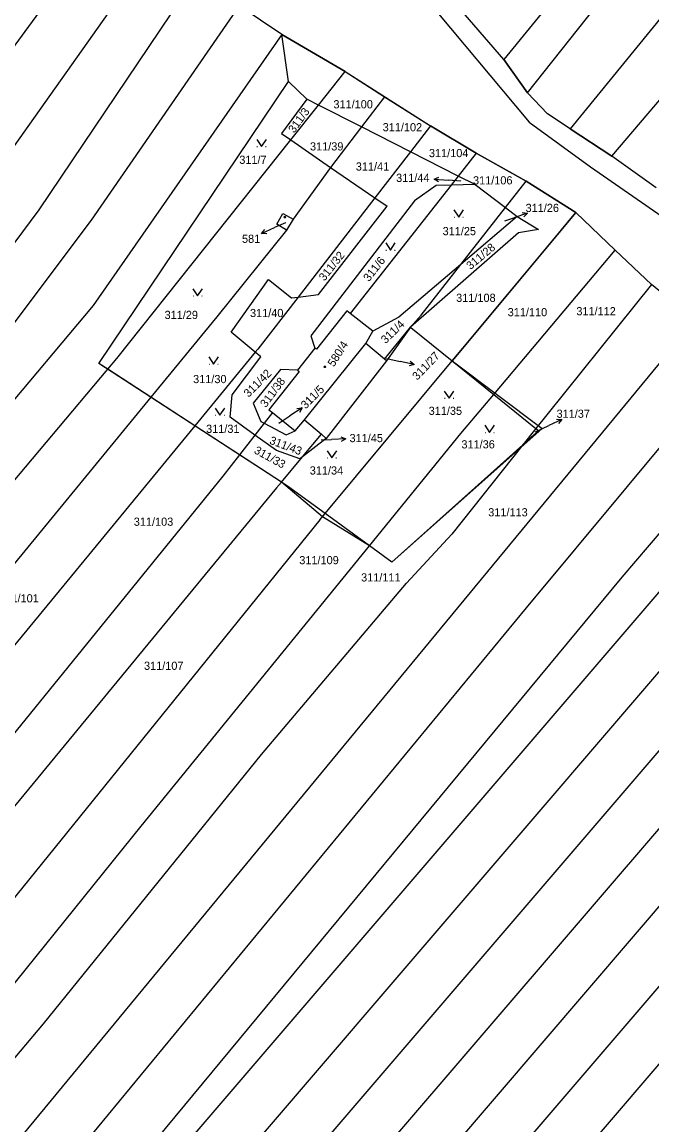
# Model space of a CAD drawing. Extents: x -580630 to -576196, y -1189024 to -1183567.
# Drawn here: x -579205 to -579073.9, y -1185934.4 to -1185704.7 of the extents above; entities that cross this region are included whole.
import ezdxf

# ---------------------------------------------------------------- set-up
doc = ezdxf.new("R2010")
doc.units = 0
for name, color, linetype in [('Vrstva 1', 7, 'Continuous'), ('Vrstva 16', 7, 'Continuous'), ('Vrstva 18', 7, 'Continuous'), ('Vrstva 19', 7, 'Continuous'), ('Vrstva 25', 7, 'Continuous'), ('Vrstva 4', 7, 'Continuous'), ('Vrstva 6', 7, 'Continuous'), ('Vrstva 63', 7, 'Continuous')]:
    doc.layers.add(name, color=color, linetype=linetype)

msp = doc.modelspace()

# ---------------------------------------------------------------- linework, layer by layer
at = {"layer": 'Vrstva 1'}
for p, q in [((-579043.29, -1185637.51), (-579104.75, -1185712.51)), ((-579099.79, -1185719.43), (-579070.36, -1185682.39)), ((-579131.33, -1185687.39), (-579099.45, -1185725.59)), ((-579082.26, -1185732.61), (-579044.89, -1185688.85)), ((-579061.52, -1185690.84), (-579090.91, -1185726.96)), ((-579104.75, -1185712.51), (-579114.98, -1185700.62)), ((-579150.91, -1185707.31), (-579159.8, -1185701.35)), ((-579137.74, -1185715.04), (-579150.91, -1185707.31)), ((-579104.75, -1185712.51), (-579099.79, -1185719.43)), ((-579137.74, -1185715.04), (-579129.57, -1185720.26)), ((-579189.01, -1185775.8), (-579149.58, -1185717.1)), ((-579149.58, -1185717.1), (-579145.75, -1185720.78)), ((-579095.65, -1185723.82), (-579099.79, -1185719.43)), ((-579145.75, -1185720.78), (-579151, -1185727.93)), ((-579143.3, -1185722.02), (-579145.75, -1185720.78)), ((-579129.57, -1185720.26), (-579119.98, -1185726.31)), ((-579134.36, -1185726.56), (-579143.3, -1185722.02)), ((-579090.91, -1185726.96), (-579095.65, -1185723.82)), ((-579110.49, -1185732.01), (-579119.98, -1185726.31)), ((-579099.45, -1185725.59), (-579086.66, -1185734.87)), ((-579151, -1185727.93), (-579149.06, -1185729.27)), ((-579124.17, -1185731.73), (-579134.36, -1185726.56)), ((-579090.91, -1185726.96), (-579082.26, -1185732.61)), ((-579149.06, -1185729.27), (-579140.77, -1185734.98)), ((-579114.22, -1185736.77), (-579124.17, -1185731.73)), ((-579100.08, -1185737.83), (-579110.49, -1185732.01)), ((-579072.99, -1185739.21), (-579082.26, -1185732.61)), ((-579140.77, -1185734.98), (-579131.58, -1185741.32)), ((-579086.66, -1185734.87), (-579070.88, -1185745.81)), ((-579110.71, -1185738.55), (-579114.22, -1185736.77)), ((-579089.72, -1185744.38), (-579100.08, -1185737.83)), ((-579118.79, -1185738.72), (-579123.31, -1185741.96)), ((-579115.7, -1185738.65), (-579118.79, -1185738.72)), ((-579110.71, -1185738.55), (-579115.7, -1185738.65)), ((-579110.71, -1185738.55), (-579104.39, -1185743.34)), ((-579123.31, -1185741.96), (-579144.91, -1185770.06)), ((-579131.58, -1185741.32), (-579129.03, -1185743.08)), ((-579151.98, -1185746.78), (-579150.71, -1185744.55)), ((-579150.71, -1185744.55), (-579148.6, -1185745.75)), ((-579143.3, -1185761.42), (-579129.03, -1185743.08)), ((-579104.39, -1185743.34), (-579101.94, -1185745.2)), ((-579089.72, -1185744.38), (-579081.53, -1185752.18)), ((-579149.99, -1185748.03), (-579151.98, -1185746.78)), ((-579148.6, -1185745.75), (-579149.99, -1185748.03)), ((-579101.94, -1185745.2), (-579113.64, -1185755.17)), ((-579101.94, -1185745.2), (-579097.53, -1185747.9)), ((-579101.63, -1185748.61), (-579124.18, -1185768.24)), ((-579097.53, -1185747.9), (-579101.63, -1185748.61)), ((-579081.53, -1185752.18), (-579073.99, -1185759.36)), ((-579113.64, -1185755.17), (-579126.56, -1185766.18)), ((-579161.51, -1185769.31), (-579153.73, -1185758.32)), ((-579153.73, -1185758.32), (-579148.93, -1185762.15)), ((-579064.92, -1185766.8), (-579073.99, -1185759.36)), ((-579148.93, -1185762.15), (-579147.54, -1185761.97)), ((-579147.54, -1185761.97), (-579143.3, -1185761.42)), ((-579137.43, -1185764.81), (-579143.75, -1185772.81)), ((-579136.69, -1185765.39), (-579137.43, -1185764.81)), ((-579132.02, -1185769.05), (-579136.69, -1185765.39)), ((-579126.56, -1185766.18), (-579132.02, -1185769.05)), ((-579156.46, -1185773.46), (-579161.51, -1185769.31)), ((-579144.91, -1185770.06), (-579144.05, -1185772.59)), ((-579133.45, -1185771.65), (-579132.02, -1185769.05)), ((-579124.18, -1185768.24), (-579129.12, -1185775.26)), ((-579124.18, -1185768.24), (-579124.08, -1185768.32)), ((-579124.08, -1185768.32), (-579115.45, -1185775.29)), ((-579129.57, -1185774.88), (-579133.45, -1185771.65)), ((-579161.29, -1185782.37), (-579155.32, -1185774.4)), ((-579155.32, -1185774.4), (-579156.46, -1185773.46)), ((-579144.05, -1185772.59), (-579147.68, -1185777.21)), ((-579143.75, -1185772.81), (-579144.05, -1185772.59)), ((-579187.16, -1185777), (-579189.01, -1185775.8)), ((-579178.19, -1185782.83), (-579187.16, -1185777)), ((-579151.24, -1185777.07), (-579156.93, -1185784.08)), ((-579147.68, -1185777.21), (-579151.24, -1185777.07)), ((-579129.12, -1185775.26), (-579141.71, -1185791.41)), ((-579129.12, -1185775.26), (-579129.57, -1185774.88)), ((-579115.45, -1185775.29), (-579106.82, -1185782.26)), ((-579147.32, -1185777.48), (-579153.63, -1185785.44)), ((-579147.68, -1185777.21), (-579147.32, -1185777.48)), ((-579169.06, -1185788.77), (-579178.19, -1185782.83)), ((-579161.69, -1185786.99), (-579161.29, -1185782.37)), ((-579106.82, -1185782.26), (-579098.03, -1185789.35)), ((-579156.93, -1185784.08), (-579155.32, -1185787.87)), ((-579153.63, -1185785.44), (-579152.89, -1185786.03)), ((-579152.89, -1185786.03), (-579148.15, -1185789.82)), ((-579080.09, -1185820.33), (-579049.55, -1185784.45)), ((-579156.55, -1185790.7), (-579161.69, -1185786.99)), ((-579155.32, -1185787.87), (-579154.62, -1185788.24)), ((-579154.62, -1185788.24), (-579150.06, -1185790.67)), ((-579148.15, -1185789.82), (-579146.19, -1185787.53)), ((-579146.19, -1185787.53), (-579142.7, -1185790.55)), ((-579043.07, -1185789.08), (-579516.28, -1186341.47)), ((-579159.77, -1185794.81), (-579169.06, -1185788.77)), ((-579152.08, -1185793.93), (-579156.55, -1185790.7)), ((-579150.06, -1185790.67), (-579148.15, -1185789.82)), ((-579142.7, -1185790.55), (-579141.71, -1185791.41)), ((-579097.45, -1185789.82), (-579100.76, -1185792.78)), ((-579098.03, -1185789.35), (-579097.45, -1185789.82)), ((-579141.71, -1185791.41), (-579146.66, -1185795.27)), ((-579100.76, -1185792.78), (-579128.06, -1185817.19)), ((-579560.3, -1186409.54), (-579034.2, -1185795.41)), ((-579151.03, -1185800.49), (-579159.77, -1185794.81)), ((-579147.17, -1185795.67), (-579152.08, -1185793.93)), ((-579146.66, -1185795.27), (-579147.17, -1185795.67)), ((-579025.51, -1185801.62), (-579550.65, -1186414.64)), ((-579149.73, -1185801.34), (-579151.03, -1185800.49)), ((-579141.9, -1185807.07), (-579149.73, -1185801.34)), ((-579541.04, -1186419.71), (-579016.85, -1185807.81)), ((-579132.7, -1185813.8), (-579141.9, -1185807.07)), ((-579128.06, -1185817.19), (-579132.7, -1185813.8)), ((-579008.27, -1185813.94), (-579531.52, -1186424.74)), ((-578999.43, -1185820.25), (-579414.73, -1186305.04)), ((-579236.45, -1186009.08), (-579080.09, -1185820.33)), ((-579398.1, -1186301.88), (-578990.93, -1185826.58))]:
    msp.add_line(p, q, dxfattribs=at)
at = {"layer": 'Vrstva 16'}
for p, q in [((-579119.254, -1185737.443), (-579116.26, -1185737.64)), ((-579113.67, -1185737.81), (-579116.26, -1185737.64)), ((-579099.783, -1185744.503), (-579102.62, -1185745.48)), ((-579150.2, -1185746.49), (-579152.47, -1185747.52)), ((-579104.48, -1185746.12), (-579102.62, -1185745.48)), ((-579155.199, -1185748.766), (-579152.47, -1185747.52)), ((-579129.07, -1185774.78), (-579126.3, -1185775.39)), ((-579123.372, -1185776.043), (-579126.3, -1185775.39)), ((-579146.727, -1185785.052), (-579149.24, -1185786.69)), ((-579151.58, -1185788.21), (-579149.24, -1185786.69)), ((-579092.648, -1185787.448), (-579095.36, -1185788.73)), ((-579098.09, -1185790.02), (-579095.36, -1185788.73)), ((-579142.76, -1185791.74), (-579140.61, -1185791.65)), ((-579137.613, -1185791.522), (-579140.61, -1185791.65))]:
    msp.add_line(p, q, dxfattribs=at)
for points in [[(-579118.289, -1185738.007), (-579119.254, -1185737.443), (-579118.223, -1185737.01)], [(-579100.892, -1185744.356), (-579099.783, -1185744.503), (-579100.566, -1185745.302)], [(-579154.082, -1185748.805), (-579155.199, -1185748.766), (-579154.497, -1185747.896)], [(-579124.239, -1185775.337), (-579123.372, -1185776.043), (-579124.457, -1185776.313)], [(-579147.837, -1185785.179), (-579146.727, -1185785.052), (-579147.291, -1185786.017)], [(-579093.766, -1185787.423), (-579092.648, -1185787.448), (-579093.338, -1185788.327)], [(-579138.633, -1185791.065), (-579137.613, -1185791.522), (-579138.591, -1185792.064)]]:
    msp.add_lwpolyline(points, dxfattribs=at)
at = {"layer": 'Vrstva 25'}
for p, q in [((-579156.11, -1185730.66), (-579156.01, -1185730.66)), ((-579154.31, -1185730.66), (-579154.21, -1185730.66)), ((-579115.06, -1185745.31), (-579114.96, -1185745.31)), ((-579113.26, -1185745.31), (-579113.16, -1185745.31)), ((-579129.26, -1185752.2), (-579129.16, -1185752.2)), ((-579127.46, -1185752.2), (-579127.36, -1185752.2)), ((-579169.42, -1185761.74), (-579169.32, -1185761.74)), ((-579167.62, -1185761.74), (-579167.52, -1185761.74)), ((-579166.09, -1185775.95), (-579165.99, -1185775.95)), ((-579164.29, -1185775.95), (-579164.19, -1185775.95)), ((-579117.06, -1185783.05), (-579116.96, -1185783.05)), ((-579115.26, -1185783.05), (-579115.16, -1185783.05)), ((-579164.76, -1185786.6), (-579164.66, -1185786.6)), ((-579162.96, -1185786.6), (-579162.86, -1185786.6)), ((-579108.63, -1185790.16), (-579108.53, -1185790.16)), ((-579106.83, -1185790.16), (-579106.73, -1185790.16)), ((-579141.46, -1185795.48), (-579141.36, -1185795.48)), ((-579139.66, -1185795.48), (-579139.56, -1185795.48))]:
    msp.add_line(p, q, dxfattribs=at)
for points in [[(-579156.16, -1185729.16), (-579155.16, -1185730.66), (-579154.16, -1185729.16)], [(-579115.11, -1185743.81), (-579114.11, -1185745.31), (-579113.11, -1185743.81)], [(-579129.31, -1185750.7), (-579128.31, -1185752.2), (-579127.31, -1185750.7)], [(-579169.47, -1185760.24), (-579168.47, -1185761.74), (-579167.47, -1185760.24)], [(-579166.14, -1185774.45), (-579165.14, -1185775.95), (-579164.14, -1185774.45)], [(-579117.11, -1185781.55), (-579116.11, -1185783.05), (-579115.11, -1185781.55)], [(-579164.81, -1185785.1), (-579163.81, -1185786.6), (-579162.81, -1185785.1)], [(-579108.68, -1185788.66), (-579107.68, -1185790.16), (-579106.68, -1185788.66)], [(-579141.51, -1185793.98), (-579140.51, -1185795.48), (-579139.51, -1185793.98)]]:
    msp.add_lwpolyline(points, dxfattribs=at)
for points in [[(-579150.22, -1185745.21), (-579150.13, -1185745.36), (-579150.22, -1185745.51), (-579150.4, -1185745.51), (-579150.49, -1185745.36), (-579150.4, -1185745.21)], [(-579141.89, -1185776.37), (-579141.8, -1185776.52), (-579141.89, -1185776.67), (-579142.07, -1185776.67), (-579142.16, -1185776.52), (-579142.07, -1185776.37)]]:
    msp.add_lwpolyline(points, close=True, dxfattribs=at)
at = {"layer": 'Vrstva 4'}
msp.add_line((-579146.19, -1185787.53), (-579133.45, -1185771.65), dxfattribs=at)
at = {"layer": 'Vrstva 6'}
for p, q in [((-579182.7, -1185676.74), (-579214.14, -1185719.94)), ((-579223.93, -1185754.88), (-579174.94, -1185685.73)), ((-579167.76, -1185693.67), (-579201.53, -1185743.83)), ((-579159.8, -1185701.35), (-579190.6, -1185745.96)), ((-579150.91, -1185707.31), (-579190.23, -1185763.7)), ((-579143.3, -1185722.02), (-579137.74, -1185715.04)), ((-579129.57, -1185720.26), (-579134.36, -1185726.56)), ((-579149.06, -1185729.27), (-579143.3, -1185722.02)), ((-579119.98, -1185726.31), (-579124.17, -1185731.73)), ((-579134.36, -1185726.56), (-579140.77, -1185734.98)), ((-579185.29, -1185774.78), (-579149.06, -1185729.27)), ((-579124.17, -1185731.73), (-579131.58, -1185741.32)), ((-579110.49, -1185732.01), (-579114.22, -1185736.77)), ((-579140.77, -1185734.98), (-579148.6, -1185745.75)), ((-579114.22, -1185736.77), (-579115.7, -1185738.65)), ((-579104.39, -1185743.34), (-579100.08, -1185737.83)), ((-579115.7, -1185738.65), (-579136.69, -1185765.39)), ((-579131.58, -1185741.32), (-579147.54, -1185761.97)), ((-579201.53, -1185743.83), (-579217.64, -1185765.38)), ((-579113.64, -1185755.17), (-579104.39, -1185743.34)), ((-579094.4, -1185750.01), (-579089.72, -1185744.38)), ((-579190.6, -1185745.96), (-579209.9, -1185771.55)), ((-579149.99, -1185748.03), (-579164.45, -1185766.09)), ((-579113.24, -1185772.64), (-579094.4, -1185750.01)), ((-579106.82, -1185782.26), (-579081.53, -1185752.18)), ((-579121.93, -1185765.76), (-579113.64, -1185755.17)), ((-579073.99, -1185759.36), (-579077.38, -1185763.58)), ((-579147.54, -1185761.97), (-579155.95, -1185772.84)), ((-579190.23, -1185763.7), (-579250.89, -1185835.97)), ((-579077.38, -1185763.58), (-579095.75, -1185786.49)), ((-579256.06, -1185998.51), (-579064.92, -1185766.8)), ((-579164.45, -1185766.09), (-579178.19, -1185782.83)), ((-579124.18, -1185768.24), (-579121.93, -1185765.76)), ((-579129.57, -1185774.88), (-579124.18, -1185768.24)), ((-579187.16, -1185777), (-579185.29, -1185774.78)), ((-579156.46, -1185773.46), (-579169.06, -1185788.77)), ((-579155.95, -1185772.84), (-579156.46, -1185773.46)), ((-579115.45, -1185775.29), (-579113.24, -1185772.64)), ((-579056.06, -1185773.75), (-579100.1, -1185826.68)), ((-579228.08, -1185825.63), (-579187.16, -1185777)), ((-579141.9, -1185807.07), (-579115.45, -1185775.29)), ((-579178.19, -1185782.83), (-579225.68, -1185840.68)), ((-579113.65, -1185790.39), (-579106.82, -1185782.26)), ((-579152.89, -1185786.03), (-579154.62, -1185788.24)), ((-579154.62, -1185788.24), (-579156.55, -1185790.7)), ((-579095.75, -1185786.49), (-579098.03, -1185789.35)), ((-579169.06, -1185788.77), (-579220.22, -1185850.96)), ((-579156.55, -1185790.7), (-579159.77, -1185794.81)), ((-579146.66, -1185795.27), (-579142.7, -1185790.55)), ((-579132.7, -1185813.8), (-579113.65, -1185790.39)), ((-579098.03, -1185789.35), (-579100.76, -1185792.78)), ((-579100.76, -1185792.78), (-579115.55, -1185811.34)), ((-579159.77, -1185794.81), (-579163.25, -1185799.24)), ((-579151.03, -1185800.49), (-579146.66, -1185795.27)), ((-579163.25, -1185799.24), (-579234.31, -1185886.86)), ((-579152.07, -1185801.73), (-579219.28, -1185883.37)), ((-579152.07, -1185801.73), (-579151.03, -1185800.49)), ((-579142.99, -1185808.38), (-579216.23, -1185898.87)), ((-579142.99, -1185808.38), (-579141.9, -1185807.07)), ((-579115.55, -1185811.34), (-579124.96, -1185821.58)), ((-579180.19, -1185872.13), (-579132.7, -1185813.8)), ((-579155.18, -1185857.23), (-579124.96, -1185821.58)), ((-579100.1, -1185826.68), (-579191.69, -1185937.77)), ((-579200.55, -1185913.3), (-579155.18, -1185857.23)), ((-579214.75, -1185914.98), (-579180.19, -1185872.13)), ((-579263.6, -1185988.16), (-579200.55, -1185913.3))]:
    msp.add_line(p, q, dxfattribs=at)
at = {"layer": 'Vrstva 63'}
for p, q in [((-579104.75, -1185712.51), (-579114.98, -1185700.62)), ((-579150.91, -1185707.31), (-579137.74, -1185715.04)), ((-579149.58, -1185717.1), (-579150.91, -1185707.31)), ((-579099.79, -1185719.43), (-579104.75, -1185712.51)), ((-579137.74, -1185715.04), (-579119.98, -1185726.31)), ((-579189.01, -1185775.8), (-579149.58, -1185717.1)), ((-579095.65, -1185723.82), (-579099.79, -1185719.43)), ((-579090.91, -1185726.96), (-579095.65, -1185723.82)), ((-579119.98, -1185726.31), (-579110.49, -1185732.01)), ((-579082.26, -1185732.61), (-579090.91, -1185726.96)), ((-579110.49, -1185732.01), (-579100.08, -1185737.83)), ((-579072.99, -1185739.21), (-579082.26, -1185732.61)), ((-579100.08, -1185737.83), (-579089.72, -1185744.38)), ((-579089.72, -1185744.38), (-579115.45, -1185775.29)), ((-579151.03, -1185800.49), (-579189.01, -1185775.8)), ((-579115.45, -1185775.29), (-579096.725, -1185789.375)), ((-579096.725, -1185789.375), (-579128.06, -1185817.19)), ((-579142.445, -1185807.725), (-579151.03, -1185800.49)), ((-579132.7, -1185813.8), (-579142.445, -1185807.725)), ((-579128.06, -1185817.19), (-579132.7, -1185813.8))]:
    msp.add_line(p, q, dxfattribs=at)

# ---------------------------------------------------------------- texts
at = {"layer": 'Vrstva 16'}
for s, p in [('311/44', (-579127.143, -1185738)), ('311/26', (-579100.187, -1185744.26)), ('581', (-579159.23, -1185750.69)), ('311/37', (-579093.74, -1185787.12)), ('311/45', (-579136.84, -1185792.19))]:
    msp.add_text(s, height=1.7, dxfattribs=at).set_placement(p)
for s, rotation, p in [('311/27', 46.06581, (-579122.751, -1185779.404)), ('311/5', 45.03448, (-579145.969, -1185785.391))]:
    msp.add_text(s, height=1.7, rotation=rotation, dxfattribs=at).set_placement(p)
at = {"layer": 'Vrstva 18'}
for s, height, p in [('311/100', 1.7, (-579140.198, -1185722.68)), ('311/102', 1.7, (-579129.945, -1185727.46)), ('311/39', 1.7, (-579145.07, -1185731.45)), ('311/104', 1.7, (-579120.311, -1185732.84)), ('311/7', 1.7, (-579159.794, -1185734.24)), ('311/41', 1.7, (-579135.535, -1185735.64)), ('311/44', 0.1, (-579113.877, -1185737.81)), ('311/106', 1.7, (-579111.131, -1185738.52)), ('311/26', 0.1, (-579104.691, -1185746.12)), ('311/25', 1.7, (-579117.464, -1185749.09)), ('311/108', 1.7, (-579114.642, -1185762.98)), ('311/29', 1.7, (-579175.347, -1185766.54)), ('311/40', 1.7, (-579157.56, -1185766.14)), ('311/110', 1.7, (-579103.913, -1185765.97)), ('311/112', 1.7, (-579089.62, -1185765.77)), ('311/27', 0.1, (-579129.279, -1185774.78)), ('311/30', 1.7, (-579169.407, -1185779.9)), ('311/35', 1.7, (-579120.367, -1185786.51)), ('311/31', 1.7, (-579166.702, -1185790.26)), ('311/5', 0.1, (-579151.749, -1185788.21)), ('311/37', 0.1, (-579098.299, -1185790.02)), ('311/45', 0.1, (-579142.969, -1185791.74)), ('311/36', 1.7, (-579113.55, -1185793.49)), ('311/34', 1.7, (-579145.12, -1185798.93)), ('311/113', 1.7, (-579107.964, -1185807.64)), ('311/103', 1.7, (-579181.758, -1185809.6)), ('311/109', 1.7, (-579147.301, -1185817.61)), ('311/111', 1.7, (-579134.429, -1185821.2)), ('311/101', 1.7, (-579209.753, -1185825.55)), ('311/107', 1.7, (-579179.631, -1185839.6))]:
    msp.add_text(s, height=height, dxfattribs=at).set_placement(p)
for s, rotation, p in [('311/3', 54.08722, (-579148.378, -1185727.958)), ('311/28', 39.93516, (-579111.656, -1185756.376)), ('311/32', 51.6235, (-579142.061, -1185758.77)), ('311/6', 51.73809, (-579132.799, -1185758.877)), ('311/4', 44.17505, (-579129.326, -1185771.788)), ('311/42', 45.03448, (-579157.865, -1185782.958)), ('311/38', 53.39967, (-579154.249, -1185785.097)), ('311/33', 331.2269, (-579156.872, -1185794.385)), ('311/43', 339.19101, (-579153.656, -1185792.471))]:
    msp.add_text(s, height=1.7, rotation=rotation, dxfattribs=at).set_placement(p)
at = {"layer": 'Vrstva 19'}
msp.add_text('581', height=0.1, dxfattribs=at).set_placement((-579150.299, -1185746.49))
msp.add_text('580/4', height=1.7, rotation=57.29578, dxfattribs=at).set_placement((-579140.109, -1185776.633))

doc.saveas('drawing.dxf')
